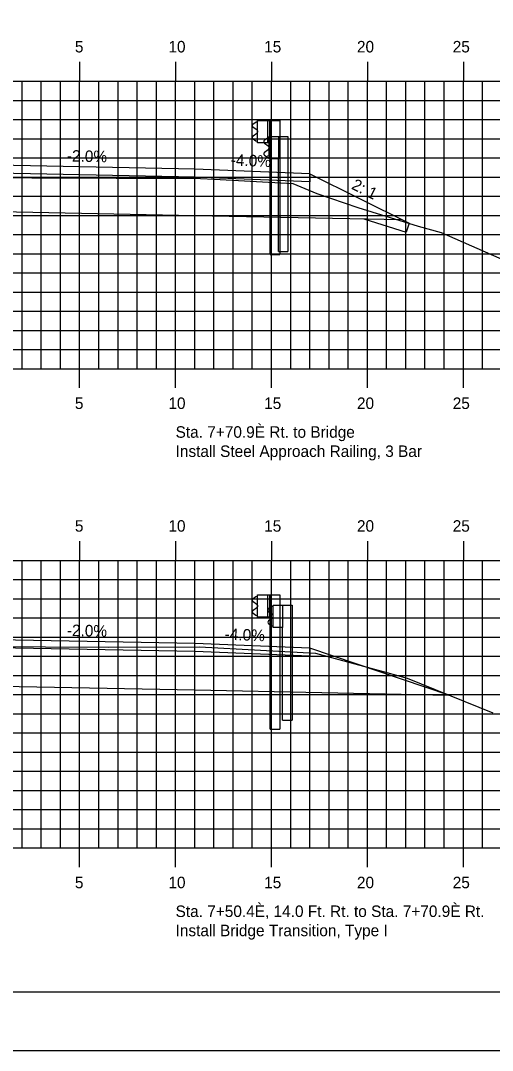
# Model space of a CAD drawing. Extents: x 2194256 to 2194747, y 863888 to 863998.
# Drawn here: x 2194478.7 to 2194503.3, y 863888.4 to 863942.1 of the extents above; entities that cross this region are included whole.
import ezdxf

# ---------------------------------------------------------------- set-up
doc = ezdxf.new("R2010")
doc.units = 0
for name, color, linetype in [('ANNOTATION', 7, 'Continuous'), ('BORDER', 7, 'Continuous'), ('D_Guardrail_Beam_Lt', 7, 'Continuous'), ('H_V ANNOTATION', 7, 'Continuous'), ('MAJOR', 7, 'Continuous'), ('MINOR', 7, 'Continuous'), ('PLOT BOUNDARY', 7, 'Continuous'), ('S_Guardrail_Beam', 7, 'Continuous'), ('S_Roadway_Centerline', 7, 'Continuous'), ('TEMPLATE', 7, 'Continuous')]:
    doc.layers.add(name, color=color, linetype=linetype)

msp = doc.modelspace()

# ---------------------------------------------------------------- linework, layer by layer
at = {"layer": 'BORDER'}
msp.add_lwpolyline([(2194401.743, 863891.446), (2194561.743, 863891.446), (2194561.743, 863996.446), (2194401.743, 863996.446)], close=True, dxfattribs=at)
at = {"layer": 'D_Guardrail_Beam_Lt'}
for p, q in [((2194490.924, 863936.798), (2194490.78, 863936.698)), ((2194491.014, 863936.819), (2194490.939, 863936.805)), ((2194491.014, 863936.902), (2194491.701, 863936.902)), ((2194491.014, 863935.736), (2194491.014, 863936.902)), ((2194491.534, 863936.902), (2194491.534, 863935.736)), ((2194491.639, 863936.902), (2194491.639, 863935.736)), ((2194491.701, 863936.902), (2194492.172, 863936.902)), ((2194491.701, 863936.902), (2194491.701, 863935.736)), ((2194492.172, 863936.902), (2194492.172, 863929.902)), ((2194490.78, 863936.555), (2194490.976, 863936.419)), ((2194491.009, 863936.354), (2194491.009, 863936.284)), ((2194490.976, 863936.22), (2194490.78, 863936.083)), ((2194490.78, 863935.94), (2194490.924, 863935.84)), ((2194490.939, 863935.834), (2194491.014, 863935.819)), ((2194491.701, 863935.736), (2194491.014, 863935.736)), ((2194491.68, 863929.902), (2194491.68, 863935.736)), ((2194491.68, 863929.902), (2194492.172, 863929.902)), ((2194491.014, 863912.069), (2194490.939, 863912.055)), ((2194491.014, 863912.152), (2194491.701, 863912.152)), ((2194491.014, 863910.986), (2194491.014, 863912.152)), ((2194491.534, 863912.152), (2194491.534, 863910.986)), ((2194491.639, 863912.152), (2194491.639, 863910.986)), ((2194491.701, 863912.152), (2194492.172, 863912.152)), ((2194491.701, 863912.152), (2194491.701, 863910.986)), ((2194492.172, 863912.152), (2194492.172, 863905.152)), ((2194490.924, 863912.048), (2194490.78, 863911.948)), ((2194490.78, 863911.805), (2194490.976, 863911.669)), ((2194491.009, 863911.604), (2194491.009, 863911.534)), ((2194490.976, 863911.47), (2194490.78, 863911.333)), ((2194490.78, 863911.19), (2194490.924, 863911.09)), ((2194490.939, 863911.084), (2194491.014, 863911.069)), ((2194491.701, 863910.986), (2194491.014, 863910.986)), ((2194491.68, 863905.152), (2194491.68, 863910.986)), ((2194491.68, 863905.152), (2194492.172, 863905.152))]:
    msp.add_line(p, q, dxfattribs=at)
for centre, major_axis, start_param, end_param in [((2194490.948, 863936.764), (-0.0417, 0), 4.907132, 5.323254), ((2194490.83, 863936.626), (-0.0877, 0), 5.323254, 7.243116), ((2194490.93, 863936.354), (0.0789, 0), 0, 0.959931), ((2194490.93, 863936.284), (0.0789, 0), 5.323254, 6.283185), ((2194490.83, 863936.012), (-0.0877, 0), 5.323254, 7.243116), ((2194490.948, 863935.874), (-0.0417, 0), 0.959931, 1.376053), ((2194490.83, 863911.876), (-0.0877, 0), 5.323254, 7.243116), ((2194490.948, 863912.014), (-0.0417, 0), 4.907132, 5.323254), ((2194490.93, 863911.604), (0.0789, 0), 0, 0.959931), ((2194490.93, 863911.534), (0.0789, 0), 5.323254, 6.283185), ((2194490.83, 863911.262), (-0.0877, 0), 5.323254, 7.243116), ((2194490.948, 863911.124), (-0.0417, 0), 0.959931, 1.376053)]:
    msp.add_ellipse(centre, major_axis=major_axis, ratio=0.995501, start_param=start_param, end_param=end_param, dxfattribs=at)
at = {"layer": 'MAJOR'}
for p, q in [((2194481.743, 863939.948), (2194481.743, 863938.946)), ((2194486.743, 863939.948), (2194486.743, 863938.946)), ((2194491.743, 863939.948), (2194491.743, 863938.946)), ((2194496.743, 863939.948), (2194496.743, 863938.946)), ((2194501.743, 863939.948), (2194501.743, 863938.946)), ((2194406.743, 863938.946), (2194546.743, 863938.946)), ((2194481.743, 863923.946), (2194481.743, 863938.946)), ((2194486.743, 863923.946), (2194486.743, 863938.946)), ((2194491.743, 863923.946), (2194491.743, 863938.946)), ((2194496.743, 863923.946), (2194496.743, 863938.946)), ((2194501.743, 863923.946), (2194501.743, 863938.946)), ((2194406.743, 863933.946), (2194546.743, 863933.946)), ((2194406.743, 863928.946), (2194546.743, 863928.946)), ((2194406.743, 863923.946), (2194546.743, 863923.946)), ((2194481.743, 863922.944), (2194481.743, 863923.946)), ((2194486.743, 863922.944), (2194486.743, 863923.946)), ((2194491.743, 863922.944), (2194491.743, 863923.946)), ((2194496.743, 863922.944), (2194496.743, 863923.946)), ((2194501.743, 863922.944), (2194501.743, 863923.946)), ((2194481.743, 863914.948), (2194481.743, 863913.946)), ((2194486.743, 863914.948), (2194486.743, 863913.946)), ((2194491.743, 863914.948), (2194491.743, 863913.946)), ((2194496.743, 863914.948), (2194496.743, 863913.946)), ((2194501.743, 863914.948), (2194501.743, 863913.946)), ((2194406.743, 863913.946), (2194546.743, 863913.946)), ((2194481.743, 863898.946), (2194481.743, 863913.946)), ((2194486.743, 863898.946), (2194486.743, 863913.946)), ((2194491.743, 863898.946), (2194491.743, 863913.946)), ((2194496.743, 863898.946), (2194496.743, 863913.946)), ((2194501.743, 863898.946), (2194501.743, 863913.946)), ((2194406.743, 863908.946), (2194546.743, 863908.946)), ((2194406.743, 863903.946), (2194546.743, 863903.946)), ((2194406.743, 863898.946), (2194546.743, 863898.946)), ((2194481.743, 863897.944), (2194481.743, 863898.946)), ((2194486.743, 863897.944), (2194486.743, 863898.946)), ((2194491.743, 863897.944), (2194491.743, 863898.946)), ((2194496.743, 863897.944), (2194496.743, 863898.946)), ((2194501.743, 863897.944), (2194501.743, 863898.946))]:
    msp.add_line(p, q, dxfattribs=at)
at = {"layer": 'MINOR'}
for p, q in [((2194478.743, 863923.946), (2194478.743, 863938.946)), ((2194479.743, 863923.946), (2194479.743, 863938.946)), ((2194480.743, 863923.946), (2194480.743, 863938.946)), ((2194482.743, 863923.946), (2194482.743, 863938.946)), ((2194483.743, 863923.946), (2194483.743, 863938.946)), ((2194484.743, 863923.946), (2194484.743, 863938.946)), ((2194485.743, 863923.946), (2194485.743, 863938.946)), ((2194487.743, 863923.946), (2194487.743, 863938.946)), ((2194488.743, 863923.946), (2194488.743, 863938.946)), ((2194489.743, 863923.946), (2194489.743, 863938.946)), ((2194490.743, 863923.946), (2194490.743, 863938.946)), ((2194492.743, 863923.946), (2194492.743, 863938.946)), ((2194493.743, 863923.946), (2194493.743, 863938.946)), ((2194494.743, 863923.946), (2194494.743, 863938.946)), ((2194495.743, 863923.946), (2194495.743, 863938.946)), ((2194497.743, 863923.946), (2194497.743, 863938.946)), ((2194498.743, 863923.946), (2194498.743, 863938.946)), ((2194499.743, 863923.946), (2194499.743, 863938.946)), ((2194500.743, 863923.946), (2194500.743, 863938.946)), ((2194502.743, 863923.946), (2194502.743, 863938.946)), ((2194406.743, 863937.946), (2194546.743, 863937.946)), ((2194406.743, 863936.946), (2194546.743, 863936.946)), ((2194406.743, 863935.946), (2194546.743, 863935.946)), ((2194406.743, 863934.946), (2194546.743, 863934.946)), ((2194406.743, 863932.946), (2194546.743, 863932.946)), ((2194406.743, 863931.946), (2194546.743, 863931.946)), ((2194406.743, 863930.946), (2194546.743, 863930.946)), ((2194406.743, 863929.946), (2194546.743, 863929.946)), ((2194406.743, 863927.946), (2194546.743, 863927.946)), ((2194406.743, 863926.946), (2194546.743, 863926.946)), ((2194406.743, 863925.946), (2194546.743, 863925.946)), ((2194406.743, 863924.946), (2194546.743, 863924.946)), ((2194478.743, 863898.946), (2194478.743, 863913.946)), ((2194479.743, 863898.946), (2194479.743, 863913.946)), ((2194480.743, 863898.946), (2194480.743, 863913.946)), ((2194482.743, 863898.946), (2194482.743, 863913.946)), ((2194483.743, 863898.946), (2194483.743, 863913.946)), ((2194484.743, 863898.946), (2194484.743, 863913.946)), ((2194485.743, 863898.946), (2194485.743, 863913.946)), ((2194487.743, 863898.946), (2194487.743, 863913.946)), ((2194488.743, 863898.946), (2194488.743, 863913.946)), ((2194489.743, 863898.946), (2194489.743, 863913.946)), ((2194490.743, 863898.946), (2194490.743, 863913.946)), ((2194492.743, 863898.946), (2194492.743, 863913.946)), ((2194493.743, 863898.946), (2194493.743, 863913.946)), ((2194494.743, 863898.946), (2194494.743, 863913.946)), ((2194495.743, 863898.946), (2194495.743, 863913.946)), ((2194497.743, 863898.946), (2194497.743, 863913.946)), ((2194498.743, 863898.946), (2194498.743, 863913.946)), ((2194499.743, 863898.946), (2194499.743, 863913.946)), ((2194500.743, 863898.946), (2194500.743, 863913.946)), ((2194502.743, 863898.946), (2194502.743, 863913.946)), ((2194406.743, 863912.946), (2194546.743, 863912.946)), ((2194406.743, 863911.946), (2194546.743, 863911.946)), ((2194406.743, 863910.946), (2194546.743, 863910.946)), ((2194406.743, 863909.946), (2194546.743, 863909.946)), ((2194406.743, 863907.946), (2194546.743, 863907.946)), ((2194406.743, 863906.946), (2194546.743, 863906.946)), ((2194406.743, 863905.946), (2194546.743, 863905.946)), ((2194406.743, 863904.946), (2194546.743, 863904.946)), ((2194406.743, 863902.946), (2194546.743, 863902.946)), ((2194406.743, 863901.946), (2194546.743, 863901.946)), ((2194406.743, 863900.946), (2194546.743, 863900.946)), ((2194406.743, 863899.946), (2194546.743, 863899.946))]:
    msp.add_line(p, q, dxfattribs=at)
at = {"layer": 'PLOT BOUNDARY'}
msp.add_lwpolyline([(2194393.65, 863888.387), (2194563.65, 863888.387), (2194563.65, 863998.387), (2194393.65, 863998.387)], close=True, dxfattribs=at)
at = {"layer": 'S_Guardrail_Beam'}
for p, q in [((2194491.519, 863935.961), (2194491.376, 863935.861)), ((2194491.376, 863935.718), (2194491.571, 863935.582)), ((2194491.618, 863935.983), (2194491.536, 863935.968)), ((2194491.618, 863936.056), (2194492.108, 863936.056)), ((2194491.618, 863934.889), (2194491.618, 863936.056)), ((2194492.108, 863936.056), (2194492.599, 863936.056)), ((2194492.108, 863936.056), (2194492.108, 863934.889)), ((2194492.599, 863936.056), (2194492.599, 863930.056)), ((2194491.571, 863935.362), (2194491.376, 863935.226)), ((2194491.605, 863935.518), (2194491.605, 863935.427)), ((2194491.376, 863935.083), (2194491.519, 863934.983)), ((2194491.536, 863934.976), (2194491.618, 863934.962)), ((2194492.108, 863934.889), (2194491.618, 863934.889)), ((2194492.108, 863930.056), (2194492.108, 863934.889)), ((2194492.108, 863930.056), (2194492.599, 863930.056)), ((2194491.733, 863911.527), (2194491.589, 863911.427)), ((2194491.831, 863911.548), (2194491.749, 863911.534)), ((2194491.831, 863911.621), (2194492.321, 863911.621)), ((2194491.831, 863910.455), (2194491.831, 863911.621)), ((2194492.321, 863911.621), (2194492.813, 863911.621)), ((2194492.321, 863911.621), (2194492.321, 863910.455)), ((2194492.813, 863911.621), (2194492.813, 863905.621)), ((2194491.589, 863911.284), (2194491.785, 863911.148)), ((2194491.818, 863911.084), (2194491.818, 863910.992)), ((2194491.785, 863910.928), (2194491.589, 863910.792)), ((2194491.589, 863910.649), (2194491.733, 863910.549)), ((2194491.749, 863910.542), (2194491.831, 863910.528)), ((2194492.321, 863910.455), (2194491.831, 863910.455)), ((2194492.321, 863905.621), (2194492.321, 863910.455)), ((2194492.321, 863905.621), (2194492.813, 863905.621))]:
    msp.add_line(p, q, dxfattribs=at)
for centre, major_axis, start_param, end_param in [((2194491.426, 863935.79), (-0.0877, 0), 5.323254, 7.243116), ((2194491.543, 863935.927), (-0.0417, 0), 4.886922, 5.323254), ((2194491.426, 863935.155), (-0.0877, 0), 5.323254, 7.243116), ((2194491.526, 863935.518), (0.0789, 0), 0, 0.959931), ((2194491.526, 863935.427), (0.0789, 0), 5.323254, 6.283185), ((2194491.543, 863935.017), (-0.0417, 0), 0.959931, 1.396263), ((2194491.757, 863911.493), (-0.0417, 0), 4.886922, 5.323254), ((2194491.64, 863911.356), (-0.0877, 0), 5.323254, 7.243116), ((2194491.739, 863911.084), (0.0789, 0), 0, 0.959931), ((2194491.739, 863910.992), (0.0789, 0), 5.323254, 6.283185), ((2194491.64, 863910.72), (-0.0877, 0), 5.323254, 7.243116), ((2194491.757, 863910.583), (-0.0417, 0), 0.959931, 1.396263)]:
    msp.add_ellipse(centre, major_axis=major_axis, ratio=0.995501, start_param=start_param, end_param=end_param, dxfattribs=at)
at = {"layer": 'S_Roadway_Centerline'}
for points in [[(2194442.863, 863927.76), (2194449.251, 863928.439), (2194450.337, 863928.603), (2194454.623, 863930.463), (2194458.623, 863931.901), (2194461.536, 863933.124), (2194462.161, 863933.415), (2194462.515, 863933.466), (2194464.085, 863933.642), (2194465.136, 863933.716), (2194465.493, 863933.756), (2194474.019, 863933.889), (2194476.568, 863933.943), (2194476.586, 863933.943), (2194479.256, 863933.911), (2194488.047, 863933.866), (2194488.748, 863933.828), (2194492.853, 863933.603), (2194494.098, 863933.09), (2194496.246, 863932.361), (2194499.381, 863931.386), (2194500.582, 863931.046), (2194505.6, 863928.851)], [(2194442.413, 863903.585), (2194454.389, 863908.554), (2194463.492, 863909.094), (2194463.809, 863909.13), (2194464.046, 863909.146), (2194465.354, 863909.317), (2194470.233, 863909.359), (2194476.647, 863909.46), (2194483.268, 863909.426), (2194487.992, 863909.437), (2194491.166, 863909.262), (2194494.029, 863909.115), (2194497.76, 863908.092), (2194498.817, 863907.801), (2194503.284, 863905.992)]]:
    msp.add_lwpolyline(points, dxfattribs=at)
at = {"layer": 'TEMPLATE'}
for p, q in [((2194487.743, 863934.356), (2194476.743, 863934.576)), ((2194487.743, 863933.939), (2194476.743, 863934.159)), ((2194493.743, 863934.116), (2194487.743, 863934.356)), ((2194493.743, 863934.116), (2194498.91, 863931.532)), ((2194498.91, 863931.532), (2194498.768, 863931.076)), ((2194487.743, 863909.606), (2194476.743, 863909.826)), ((2194487.743, 863909.189), (2194476.743, 863909.409)), ((2194493.743, 863909.366), (2194487.743, 863909.606)), ((2194500.982, 863906.924), (2194493.743, 863909.366))]:
    msp.add_line(p, q, dxfattribs=at)
for points in [[(2194493.743, 863933.699), (2194493.743, 863934.116), (2194493.743, 863933.699), (2194487.743, 863933.939)], [(2194454.958, 863931.723), (2194465.743, 863931.939), (2194476.743, 863932.159), (2194487.743, 863931.939), (2194498.527, 863931.723)], [(2194496.561, 863931.763), (2194498.768, 863931.076)], [(2194493.743, 863908.949), (2194493.743, 863909.366), (2194493.743, 863908.949), (2194487.743, 863909.189)], [(2194450.357, 863906.881), (2194465.743, 863907.189), (2194476.743, 863907.409), (2194487.743, 863907.189), (2194500.982, 863906.924)]]:
    msp.add_lwpolyline(points, dxfattribs=at)

# ---------------------------------------------------------------- texts
at = {"layer": 'ANNOTATION'}
for s, rotation, p in [('-2.0%', 358.8542, (2194481.071, 863934.756)), ('-4.0%', 357.7094, (2194489.609, 863934.548)), ('2: 1', 333.4349, (2194495.87, 863933.351)), ('-2.0%', 358.8542, (2194481.071, 863910.006)), ('-4.0%', 357.7094, (2194489.292, 863909.811))]:
    msp.add_text(s, height=0.6, rotation=rotation, dxfattribs=at).set_placement(p)
for s, p in [('Sta. 7+70.9È Rt. to Bridge', (2194486.743, 863920.346)), ('Install Steel Approach Railing, 3 Bar', (2194486.743, 863919.344)), ('Sta. 7+50.4È, 14.0 Ft. Rt. to Sta. 7+70.9È Rt.', (2194486.743, 863895.346)), ('Install Bridge Transition, Type I', (2194486.743, 863894.344))]:
    msp.add_text(s, height=0.6, dxfattribs=at).set_placement(p)
at = {"layer": 'H_V ANNOTATION'}
for s, p in [('5', (2194481.494, 863940.446)), ('10', (2194486.368, 863940.446)), ('15', (2194491.36, 863940.446)), ('20', (2194496.197, 863940.446)), ('25', (2194501.189, 863940.446)), ('5', (2194481.494, 863921.846)), ('10', (2194486.368, 863921.846)), ('15', (2194491.36, 863921.846)), ('20', (2194496.197, 863921.846)), ('25', (2194501.189, 863921.846)), ('5', (2194481.494, 863915.446)), ('10', (2194486.368, 863915.446)), ('15', (2194491.36, 863915.446)), ('20', (2194496.197, 863915.446)), ('25', (2194501.189, 863915.446)), ('5', (2194481.494, 863896.846)), ('10', (2194486.368, 863896.846)), ('15', (2194491.36, 863896.846)), ('20', (2194496.197, 863896.846)), ('25', (2194501.189, 863896.846))]:
    msp.add_text(s, height=0.6, dxfattribs=at).set_placement(p)

doc.saveas('drawing.dxf')
